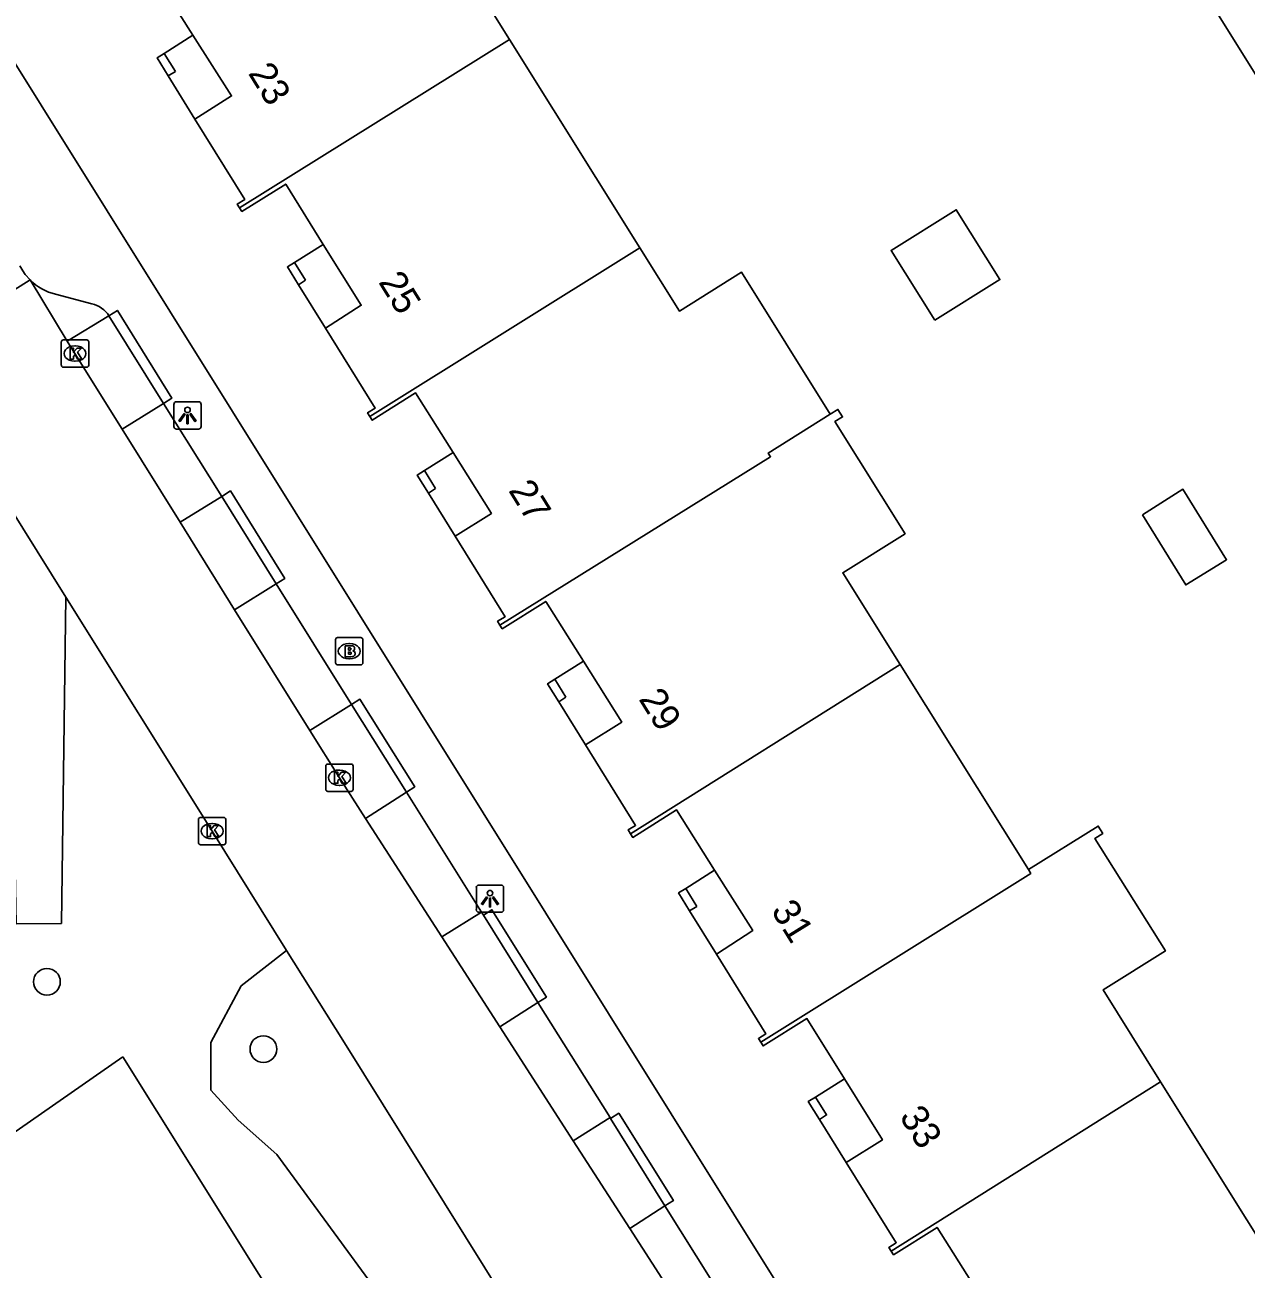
# Model space of a CAD drawing. Extents: x 158838 to 160074, y 386376 to 387776.
# Drawn here: x 159155.15 to 159199.82, y 387065.02 to 387110.53 of the extents above; entities that cross this region are included whole.
import ezdxf

# ---------------------------------------------------------------- set-up
doc = ezdxf.new("R2010")
doc.units = 0
for name, color, linetype in [('IMGEO_Boom', 7, 'Continuous'), ('IMGEO_Brandkraan', 7, 'Continuous'), ('IMGEO_Groenvoorziening', 7, 'Continuous'), ('IMGEO_Kolk', 7, 'Continuous'), ('IMGEO_Lichtpunt', 7, 'Continuous'), ('IMGEO_Pand', 7, 'Continuous'), ('IMGEO_Pand_nummerreeks', 7, 'Continuous'), ('IMGEO_Pand_overbouw', 7, 'Continuous'), ('IMGEO_Rijbaan_lokaal_open', 7, 'Continuous'), ('IMGEO_Voetpad_open', 7, 'Continuous')]:
    doc.layers.add(name, color=color, linetype=linetype)

msp = doc.modelspace()

# ---------------------------------------------------------------- linework, layer by layer
at = {"layer": 'IMGEO_Boom'}
for centre in [(159155.961, 387075.529), (159163.879, 387073.067)]:
    msp.add_circle(centre, 0.489, dxfattribs=at)
at = {"layer": 'IMGEO_Brandkraan'}
for p, q in [((159166.517, 387087.194), (159166.517, 387088.046)), ((159166.592, 387088.12), (159167.444, 387088.12)), ((159167.005, 387087.9), (159167.03, 387087.9)), ((159167.518, 387088.046), (159167.518, 387087.194)), ((159167.444, 387087.12), (159166.592, 387087.12)), ((159167.028, 387087.34), (159167.003, 387087.34))]:
    msp.add_line(p, q, dxfattribs=at)
for points in [[(159166.517, 387087.194), (159166.517, 387088.046)], [(159166.592, 387088.12), (159167.444, 387088.12)], [(159167.518, 387088.046), (159167.518, 387087.194)], [(159166.865, 387087.82), (159166.865, 387087.42), (159167.078, 387087.42)], [(159167.096, 387087.82), (159166.865, 387087.82)], [(159167.044, 387087.739), (159166.99, 387087.739), (159166.99, 387087.663)], [(159166.99, 387087.663), (159167.043, 387087.663)], [(159167.052, 387087.587), (159166.99, 387087.587), (159166.99, 387087.506)], [(159166.99, 387087.506), (159167.052, 387087.506)], [(159167.444, 387087.12), (159166.592, 387087.12)]]:
    msp.add_lwpolyline(points, dxfattribs=at)
for centre, radius, start, end in [((159166.594, 387088.044), 0.0765, 91.552, 178.448), ((159166.594, 387088.044), 0.0765, 91.552, 178.448), ((159167.442, 387088.044), 0.0765, 1.552, 88.448), ((159167.442, 387088.044), 0.0765, 1.552, 88.448), ((159167.045, 387087.701), 0.0379, 267.8285, 90.9355), ((159167.053, 387087.546), 0.0404, 269.8759, 90.5077), ((159167.084, 387087.671), 0.251, 268.6676, 293.5347), ((159167.1, 387087.675), 0.145, 59.4692, 91.5367), ((159167.125, 387087.722), 0.0922, 285.5137, 58.1501), ((159167.13, 387087.53), 0.105, 301.3115, 78.989), ((159166.594, 387087.196), 0.0765, 181.552, 268.448), ((159166.594, 387087.196), 0.0765, 181.552, 268.448), ((159167.442, 387087.196), 0.0765, 271.552, 358.448), ((159167.442, 387087.196), 0.0765, 271.552, 358.448)]:
    msp.add_arc(centre, radius, start, end, dxfattribs=at)
for centre, major_axis, ratio, start_param, end_param in [((159167.004, 387087.62), (-0.387, 0.002), 0.722429, 4.712389, 7.853982), ((159167.029, 387087.62), (-0.39, 0.002), 0.717154, 1.570796, 4.712389)]:
    msp.add_ellipse(centre, major_axis=major_axis, ratio=ratio, start_param=start_param, end_param=end_param, dxfattribs=at)
at = {"layer": 'IMGEO_Groenvoorziening'}
for points in [[(159156.656, 387089.592), (159156.492, 387077.665), (159154.841, 387077.644), (159154.788, 387080.232), (159154.777, 387080.645), (159154.665, 387081.712), (159154.435, 387082.76), (159154.09, 387083.777), (159153.633, 387084.748), (159153.071, 387085.662), (159152.41, 387086.508), (159141.336, 387093.187)], [(159164.727, 387076.677), (159163.071, 387075.375), (159161.956, 387073.311), (159161.961, 387071.56), (159162.951, 387070.464), (159164.365, 387069.21), (159170.06, 387061.436), (159176.347, 387051.538), (159181.489, 387043.315), (159183.449, 387039.236)], [(159158.739, 387072.783), (159178.64, 387040.984), (159166.329, 387032.414), (159146.428, 387064.213), (159158.739, 387072.783)]]:
    msp.add_lwpolyline(points, dxfattribs=at)
at = {"layer": 'IMGEO_Kolk'}
for p, q in [((159156.487, 387098.08), (159156.487, 387098.932)), ((159156.562, 387099.006), (159157.414, 387099.006)), ((159157.488, 387098.932), (159157.488, 387098.08)), ((159156.975, 387098.786), (159157, 387098.786)), ((159157.414, 387098.006), (159156.562, 387098.006)), ((159156.998, 387098.226), (159156.973, 387098.226)), ((159166.16, 387082.567), (159166.16, 387083.419)), ((159166.235, 387083.493), (159167.087, 387083.493)), ((159167.161, 387083.419), (159167.161, 387082.567)), ((159166.648, 387083.273), (159166.673, 387083.273)), ((159167.087, 387082.493), (159166.235, 387082.493)), ((159166.671, 387082.713), (159166.646, 387082.713)), ((159161.578, 387081.541), (159162.43, 387081.541)), ((159161.503, 387080.615), (159161.503, 387081.467)), ((159161.991, 387081.321), (159162.016, 387081.321)), ((159162.504, 387081.467), (159162.504, 387080.615)), ((159162.014, 387080.761), (159161.989, 387080.761)), ((159162.43, 387080.541), (159161.578, 387080.541))]:
    msp.add_line(p, q, dxfattribs=at)
for points in [[(159156.487, 387098.08), (159156.487, 387098.932)], [(159156.562, 387099.006), (159157.414, 387099.006)], [(159157.488, 387098.932), (159157.488, 387098.08)], [(159156.808, 387098.706), (159156.931, 387098.706), (159156.931, 387098.555), (159157.061, 387098.706), (159157.225, 387098.706), (159157.079, 387098.555), (159157.232, 387098.306), (159157.08, 387098.306), (159156.995, 387098.47), (159156.931, 387098.403), (159156.931, 387098.306), (159156.808, 387098.306), (159156.808, 387098.706)], [(159157.414, 387098.006), (159156.562, 387098.006)], [(159166.16, 387082.567), (159166.16, 387083.419)], [(159166.235, 387083.493), (159167.087, 387083.493)], [(159167.161, 387083.419), (159167.161, 387082.567)], [(159166.481, 387083.193), (159166.604, 387083.193), (159166.604, 387083.042), (159166.734, 387083.193), (159166.898, 387083.193), (159166.752, 387083.042), (159166.905, 387082.793), (159166.753, 387082.793), (159166.668, 387082.957), (159166.604, 387082.89), (159166.604, 387082.793), (159166.481, 387082.793), (159166.481, 387083.193)], [(159167.087, 387082.493), (159166.235, 387082.493)], [(159161.578, 387081.541), (159162.43, 387081.541)], [(159161.503, 387080.615), (159161.503, 387081.467)], [(159161.824, 387081.241), (159161.947, 387081.241), (159161.947, 387081.09), (159162.077, 387081.241), (159162.241, 387081.241), (159162.095, 387081.09), (159162.248, 387080.841), (159162.096, 387080.841), (159162.011, 387081.005), (159161.947, 387080.938), (159161.947, 387080.841), (159161.824, 387080.841), (159161.824, 387081.241)], [(159162.504, 387081.467), (159162.504, 387080.615)], [(159162.43, 387080.541), (159161.578, 387080.541)]]:
    msp.add_lwpolyline(points, dxfattribs=at)
for centre, start, end in [((159156.564, 387098.93), 91.552, 178.448), ((159156.564, 387098.93), 91.552, 178.448), ((159157.412, 387098.93), 1.552, 88.448), ((159157.412, 387098.93), 1.552, 88.448), ((159156.564, 387098.082), 181.552, 268.448), ((159156.564, 387098.082), 181.552, 268.448), ((159157.412, 387098.082), 271.552, 358.448), ((159157.412, 387098.082), 271.552, 358.448), ((159166.237, 387083.417), 91.552, 178.448), ((159166.237, 387083.417), 91.552, 178.448), ((159167.085, 387083.417), 1.552, 88.448), ((159167.085, 387083.417), 1.552, 88.448), ((159166.237, 387082.569), 181.552, 268.448), ((159166.237, 387082.569), 181.552, 268.448), ((159167.085, 387082.569), 271.552, 358.448), ((159167.085, 387082.569), 271.552, 358.448), ((159161.58, 387081.465), 91.552, 178.448), ((159161.58, 387081.465), 91.552, 178.448), ((159162.428, 387081.465), 1.552, 88.448), ((159162.428, 387081.465), 1.552, 88.448), ((159161.58, 387080.617), 181.552, 268.448), ((159161.58, 387080.617), 181.552, 268.448), ((159162.428, 387080.617), 271.552, 358.448), ((159162.428, 387080.617), 271.552, 358.448)]:
    msp.add_arc(centre, 0.0765, start, end, dxfattribs=at)
for centre, major_axis, ratio, start_param, end_param in [((159156.974, 387098.506), (-0.387, 0.002), 0.722429, 4.712389, 7.853982), ((159156.999, 387098.506), (-0.39, 0.002), 0.717154, 1.570796, 4.712389), ((159166.647, 387082.993), (-0.387, 0.002), 0.722429, 4.712389, 7.853982), ((159166.672, 387082.993), (-0.39, 0.002), 0.717154, 1.570796, 4.712389), ((159161.99, 387081.041), (-0.387, 0.002), 0.722429, 4.712389, 7.853982), ((159162.015, 387081.041), (-0.39, 0.002), 0.717154, 1.570796, 4.712389)]:
    msp.add_ellipse(centre, major_axis=major_axis, ratio=ratio, start_param=start_param, end_param=end_param, dxfattribs=at)
at = {"layer": 'IMGEO_Lichtpunt'}
for p, q in [((159160.603, 387096.648), (159160.603, 387095.841)), ((159160.603, 387096.648), (159160.603, 387095.841)), ((159161.505, 387096.743), (159160.697, 387096.743)), ((159161.505, 387096.743), (159160.697, 387096.743)), ((159161.599, 387095.841), (159161.599, 387096.648)), ((159161.599, 387095.841), (159161.599, 387096.648)), ((159160.697, 387095.747), (159161.505, 387095.747)), ((159160.697, 387095.747), (159161.505, 387095.747)), ((159171.667, 387078.974), (159171.667, 387078.167)), ((159171.667, 387078.974), (159171.667, 387078.167)), ((159172.569, 387079.069), (159171.761, 387079.069)), ((159172.569, 387079.069), (159171.761, 387079.069)), ((159172.663, 387078.167), (159172.663, 387078.974)), ((159172.663, 387078.167), (159172.663, 387078.974)), ((159171.761, 387078.073), (159172.569, 387078.073)), ((159171.761, 387078.073), (159172.569, 387078.073))]:
    msp.add_line(p, q, dxfattribs=at)
for points in [[(159160.977, 387096.312), (159161.016, 387096.284), (159160.828, 387096.022), (159160.79, 387096.049), (159160.977, 387096.312)], [(159161.079, 387096.264), (159161.126, 387096.264), (159161.126, 387095.942), (159161.079, 387095.942), (159161.079, 387096.264)], [(159161.189, 387096.284), (159161.227, 387096.311), (159161.414, 387096.049), (159161.375, 387096.021), (159161.189, 387096.284)], [(159172.041, 387078.638), (159172.08, 387078.61), (159171.892, 387078.348), (159171.854, 387078.375), (159172.041, 387078.638)], [(159172.143, 387078.59), (159172.19, 387078.59), (159172.19, 387078.268), (159172.143, 387078.268), (159172.143, 387078.59)], [(159172.253, 387078.61), (159172.291, 387078.637), (159172.478, 387078.375), (159172.439, 387078.347), (159172.253, 387078.61)]]:
    msp.add_lwpolyline(points, dxfattribs=at)
for centre in [(159161.102, 387096.446), (159172.166, 387078.772)]:
    msp.add_circle(centre, 0.0994, dxfattribs=at)
for centre, start, end in [((159160.697, 387096.648), 90, 180), ((159160.697, 387096.648), 90, 180), ((159161.505, 387096.648), 0, 90), ((159161.505, 387096.648), 0, 90), ((159160.697, 387095.841), 180, 270), ((159160.697, 387095.841), 180, 270), ((159161.505, 387095.841), 270, 0), ((159161.505, 387095.841), 270, 360), ((159171.761, 387078.974), 90, 180), ((159171.761, 387078.974), 90, 180), ((159172.569, 387078.974), 0, 90), ((159172.569, 387078.974), 0, 90), ((159171.761, 387078.167), 180, 270), ((159171.761, 387078.167), 180, 270), ((159172.569, 387078.167), 270, 0), ((159172.569, 387078.167), 270, 360)]:
    msp.add_arc(centre, 0.0946, start, end, dxfattribs=at)
at = {"layer": 'IMGEO_Pand'}
for points in [[(159168.101, 387117.642), (159172.882, 387109.997)], [(159200.658, 387106.098), (159200.573, 387106.234), (159201.396, 387106.748), (159196.797, 387114.109), (159196.517, 387113.934), (159196.432, 387114.069)], [(159163.007, 387103.839), (159162.923, 387103.975), (159163.195, 387104.143), (159161.375, 387107.083), (159162.712, 387107.93), (159161.303, 387110.151), (159159.916, 387112.337), (159158.327, 387111.329), (159158.243, 387111.464)], [(159163.007, 387103.839), (159172.882, 387109.997)], [(159172.882, 387109.997), (159177.653, 387102.368)], [(159160.66, 387108.827), (159160.396, 387108.664), (159159.991, 387109.319), (159160.253, 387109.485), (159160.66, 387108.827)], [(159167.774, 387096.204), (159167.69, 387096.34), (159167.961, 387096.508), (159166.146, 387099.434), (159167.456, 387100.274), (159166.069, 387102.498), (159164.694, 387104.703), (159163.091, 387103.703), (159163.007, 387103.839)], [(159188.433, 387099.725), (159186.837, 387102.278), (159189.22, 387103.768), (159190.816, 387101.215), (159188.433, 387099.725)], [(159177.653, 387102.368), (159167.774, 387096.204)], [(159177.653, 387102.368), (159179.097, 387100.059), (159181.37, 387101.48), (159184.615, 387096.288)], [(159165.424, 387101.187), (159165.161, 387101.024), (159164.755, 387101.678), (159165.018, 387101.842), (159165.424, 387101.187)], [(159172.532, 387088.578), (159172.447, 387088.714), (159172.719, 387088.883), (159170.894, 387091.824), (159172.218, 387092.657), (159170.818, 387094.883), (159169.445, 387097.066), (159167.858, 387096.068), (159167.774, 387096.204)], [(159172.532, 387088.578), (159182.429, 387094.731), (159182.344, 387094.867), (159184.615, 387096.288)], [(159184.615, 387096.288), (159184.895, 387096.463), (159185.065, 387096.191), (159184.785, 387096.017), (159187.35, 387091.914), (159185.07, 387090.488), (159187.169, 387087.132)], [(159170.177, 387093.568), (159169.914, 387093.405), (159169.508, 387094.059), (159169.77, 387094.224), (159170.177, 387093.568)], [(159196.033, 387092.602), (159197.617, 387090.043), (159199.109, 387090.966), (159197.513, 387093.545), (159196.033, 387092.602)], [(159177.305, 387080.945), (159177.22, 387081.082), (159177.492, 387081.251), (159175.662, 387084.194), (159176.988, 387085.028), (159175.587, 387087.254), (159174.208, 387089.444), (159172.616, 387088.442), (159172.532, 387088.578)], [(159177.305, 387080.945), (159187.169, 387087.132)], [(159187.169, 387087.132), (159191.861, 387079.631)], [(159174.943, 387085.937), (159174.68, 387085.773), (159174.273, 387086.427), (159174.535, 387086.592), (159174.943, 387085.937)], [(159182.069, 387073.317), (159181.985, 387073.453), (159182.256, 387073.621), (159180.446, 387076.544), (159181.775, 387077.407), (159180.381, 387079.613), (159178.987, 387081.82), (159177.389, 387080.81), (159177.305, 387080.945)], [(159191.861, 387079.631), (159194.412, 387081.226), (159194.581, 387080.955), (159194.293, 387080.775), (159196.869, 387076.656), (159194.589, 387075.23), (159196.693, 387071.865)], [(159191.861, 387079.631), (159191.946, 387079.495), (159182.069, 387073.317)], [(159179.731, 387078.288), (159179.467, 387078.125), (159179.062, 387078.78), (159179.324, 387078.946), (159179.731, 387078.288)], [(159186.843, 387065.678), (159186.758, 387065.814), (159187.029, 387065.984), (159185.199, 387068.918), (159186.523, 387069.743), (159185.132, 387071.975), (159183.756, 387074.181), (159182.153, 387073.181), (159182.069, 387073.317)], [(159186.843, 387065.678), (159196.693, 387071.865)], [(159196.693, 387071.865), (159201.459, 387064.245)], [(159184.071, 387071.314), (159184.478, 387070.661), (159184.215, 387070.497), (159183.808, 387071.15), (159184.071, 387071.314)], [(159191.612, 387058.044), (159191.527, 387058.181), (159191.799, 387058.351), (159189.968, 387061.3), (159191.297, 387062.136), (159189.896, 387064.362), (159188.521, 387066.546), (159186.927, 387065.543), (159186.843, 387065.678)]]:
    msp.add_lwpolyline(points, dxfattribs=at)
at = {"layer": 'IMGEO_Pand_overbouw'}
for points in [[(159161.375, 387107.083), (159162.712, 387107.93), (159161.303, 387110.151), (159160.253, 387109.485), (159159.991, 387109.319), (159160.396, 387108.664)], [(159166.146, 387099.434), (159167.456, 387100.274), (159166.069, 387102.498), (159165.018, 387101.842), (159164.755, 387101.678), (159165.161, 387101.024)], [(159170.894, 387091.824), (159172.218, 387092.657), (159170.818, 387094.883), (159169.77, 387094.224), (159169.508, 387094.059), (159169.914, 387093.405)], [(159175.662, 387084.194), (159176.988, 387085.028), (159175.587, 387087.254), (159174.535, 387086.592), (159174.273, 387086.427), (159174.68, 387085.773)], [(159180.446, 387076.544), (159181.775, 387077.407), (159180.381, 387079.613), (159179.324, 387078.946), (159179.062, 387078.78), (159179.467, 387078.125)], [(159185.199, 387068.918), (159186.523, 387069.743), (159185.132, 387071.975), (159184.071, 387071.314), (159183.808, 387071.15), (159184.215, 387070.497)]]:
    msp.add_lwpolyline(points, close=True, dxfattribs=at)
at = {"layer": 'IMGEO_Rijbaan_lokaal_open'}
for points in [[(159154.966, 387101.718), (159155.081, 387101.534), (159155.167, 387101.398), (159155.342, 387101.198)], [(159155.342, 387101.198), (159151.054, 387098.492)], [(159156.706, 387098.96), (159155.342, 387101.198)], [(159158.708, 387095.74), (159156.983, 387098.506), (159156.706, 387098.96)], [(159151.054, 387098.492), (159152.973, 387095.484), (159156.656, 387089.592)], [(159160.832, 387092.334), (159158.708, 387095.74)], [(159162.825, 387089.138), (159160.832, 387092.334)], [(159156.656, 387089.592), (159162.001, 387081.041), (159164.727, 387076.677)], [(159165.58, 387084.718), (159162.825, 387089.138)], [(159167.615, 387081.505), (159166.656, 387082.993), (159165.58, 387084.718)], [(159170.405, 387077.174), (159167.615, 387081.505)], [(159172.528, 387073.88), (159170.405, 387077.174)], [(159186.829, 387041.329), (159185.946, 387042.748), (159176.052, 387058.552), (159174.992, 387060.245), (159166.779, 387073.393), (159164.727, 387076.677)], [(159175.21, 387069.718), (159172.528, 387073.88)], [(159177.281, 387066.504), (159175.21, 387069.718)], [(159180.204, 387061.884), (159179.375, 387063.255), (159177.281, 387066.504)]]:
    msp.add_lwpolyline(points, dxfattribs=at)
at = {"layer": 'IMGEO_Voetpad_open'}
for points in [[(159224.402, 387000.372), (159224.237, 387000.328), (159224.069, 387000.298), (159223.899, 387000.284), (159223.728, 387000.285), (159223.558, 387000.302), (159223.391, 387000.333), (159223.226, 387000.38), (159223.067, 387000.44), (159222.913, 387000.515), (159222.767, 387000.603), (159222.63, 387000.704), (159222.501, 387000.817), (159222.384, 387000.941), (159222.278, 387001.075), (159158.165, 387103.724), (159143.549, 387127.119), (159138.432, 387135.312), (159131.202, 387146.887)], [(159156.277, 387100.674), (159157.6, 387100.327)], [(159156.706, 387098.96), (159158.228, 387099.888)], [(159158.228, 387099.888), (159158.539, 387100.082), (159160.534, 387096.878), (159160.223, 387096.685)], [(159160.223, 387096.685), (159158.228, 387099.888)], [(159160.223, 387096.685), (159158.708, 387095.74)], [(159160.223, 387096.685), (159162.355, 387093.284)], [(159162.355, 387093.284), (159162.671, 387093.481), (159164.662, 387090.283), (159164.347, 387090.087)], [(159160.832, 387092.334), (159162.355, 387093.284)], [(159164.347, 387090.087), (159162.355, 387093.284)], [(159164.347, 387090.087), (159162.825, 387089.138)], [(159164.347, 387090.087), (159167.102, 387085.667)], [(159165.58, 387084.718), (159167.102, 387085.667)], [(159167.102, 387085.667), (159167.411, 387085.86), (159169.416, 387082.66), (159169.107, 387082.466)], [(159169.107, 387082.466), (159167.102, 387085.667)], [(159169.107, 387082.466), (159167.615, 387081.505)], [(159169.107, 387082.466), (159171.854, 387078.079)], [(159170.405, 387077.174), (159171.854, 387078.079)], [(159171.854, 387078.079), (159171.923, 387077.968)], [(159171.923, 387077.968), (159172.234, 387078.162), (159174.228, 387074.969), (159173.915, 387074.774)], [(159173.915, 387074.774), (159171.923, 387077.968)], [(159173.915, 387074.774), (159172.528, 387073.88)], [(159173.915, 387074.774), (159176.559, 387070.56)], [(159176.575, 387070.534), (159176.877, 387070.722), (159178.874, 387067.524), (159178.566, 387067.332)], [(159175.21, 387069.718), (159176.559, 387070.56)], [(159176.559, 387070.56), (159176.575, 387070.534)], [(159178.566, 387067.332), (159176.575, 387070.534)], [(159178.566, 387067.332), (159177.281, 387066.504)], [(159178.566, 387067.332), (159181.492, 387062.662)]]:
    msp.add_lwpolyline(points, dxfattribs=at)
for centre, radius, start, end in [((159156.751, 387102.616), 1.999, 225.1797, 256.2853), ((159157.402, 387099.375), 0.972, 31.8435, 78.246)]:
    msp.add_arc(centre, radius, start, end, dxfattribs=at)

# ---------------------------------------------------------------- texts
at = {"layer": 'IMGEO_Pand_nummerreeks'}
for s, rotation, p in [('23', 301.7588, (159163.301, 387108.76)), ('25', 301.8047, (159168.065, 387101.123)), ('27', 301.8161, (159172.82, 387093.502)), ('29', 301.8792, (159177.585, 387085.872)), ('31', 301.7646, (159182.426, 387078.134)), ('33', 301.9422, (159187.119, 387070.602))]:
    msp.add_text(s, height=1, rotation=rotation, dxfattribs=at).set_placement(p)

doc.saveas('drawing.dxf')
